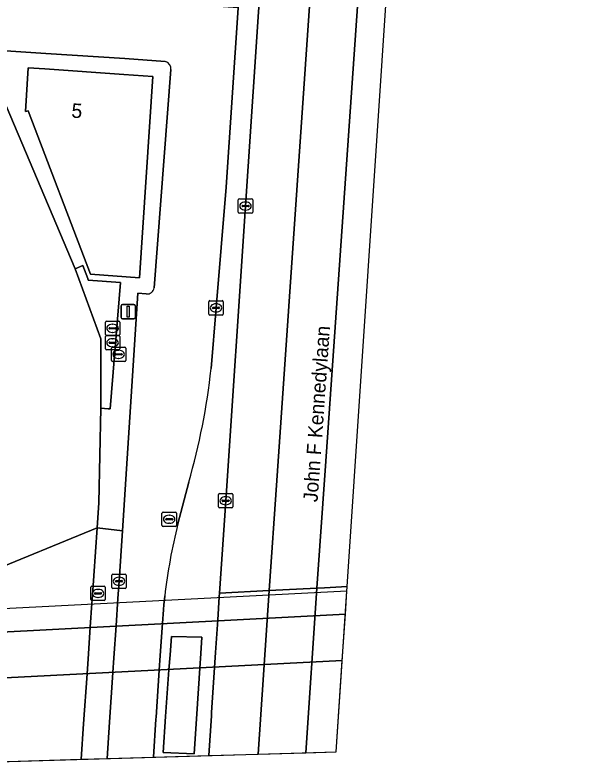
# Model space of a CAD drawing. Extents: x 161084 to 161928, y 385354 to 386522.
# Drawn here: x 161826.1 to 161866, y 385382.7 to 385434.6 of the extents above; entities that cross this region are included whole.
import ezdxf

# ---------------------------------------------------------------- set-up
doc = ezdxf.new("R2010")
doc.units = 0
for name, color, linetype in [('IMGEO_Berm_groen', 7, 'Continuous'), ('IMGEO_Berm_open', 7, 'Continuous'), ('IMGEO_Dek', 7, 'Continuous'), ('IMGEO_Fietspad_gesloten', 7, 'Continuous'), ('IMGEO_Kolk', 7, 'Continuous'), ('IMGEO_Lichtmast', 7, 'Continuous'), ('IMGEO_Openbare_ruimte_label', 7, 'Continuous'), ('IMGEO_Pand', 7, 'Continuous'), ('IMGEO_Pand_nummerreeks', 7, 'Continuous'), ('IMGEO_Pijler', 7, 'Continuous'), ('IMGEO_Rijbaan_lokaal_gesloten', 7, 'Continuous'), ('IMGEO_Rijbaan_lokaal_open', 7, 'Continuous'), ('IMGEO_Rijbaan_regionaal_gesloten', 7, 'Continuous'), ('IMGEO_Rioolput', 7, 'Continuous'), ('IMGEO_Terreindeel_open', 7, 'Continuous'), ('IMGEO_Voetpad_gesloten', 7, 'Continuous'), ('IMGEO_Voetpad_open', 7, 'Continuous')]:
    doc.layers.add(name, color=color, linetype=linetype)

msp = doc.modelspace()

# ---------------------------------------------------------------- linework, layer by layer
at = {"layer": 'IMGEO_Berm_groen'}
msp.add_lwpolyline([(161825.32, 385406.42), (161823.9, 385395.702), (161831.815, 385398.932), (161831.934, 385400.658), (161832.079, 385407.241), (161832.079, 385412.061), (161830.301, 385416.92), (161824.454, 385430.65), (161824.424, 385432.14), (161824.225, 385436.183), (161824.284, 385438.46), (161825.312, 385447.692), (161826.012, 385452.879), (161826.576, 385455.009), (161827.549, 385454.732), (161828.52, 385458.222), (161833.131, 385474.795), (161836.157, 385474.321), (161836.649, 385474.584), (161839.053, 385476.363)], dxfattribs=at)
at = {"layer": 'IMGEO_Berm_open'}
for points in [[(161839.562, 385383.109), (161839.747, 385385.876), (161839.761, 385386.097), (161839.971, 385389.239), (161840.039, 385390.264), (161840.191, 385392.532), (161840.297, 385394.134), (161840.315, 385394.398), (161840.742, 385400.813), (161842.12, 385421.284), (161843.55, 385442.735), (161844.924, 385463.175), (161845.309, 385468.395)], [(161843.117, 385463.877), (161843.398, 385461.787), (161842.893, 385454.265), (161841.605, 385435.058), (161840.769, 385422.585), (161840.069, 385414.21), (161839.728, 385410.002)], [(161838.182, 385402.099), (161837.422, 385399.201)], [(161836.513, 385394.202), (161836.485, 385393.943), (161836.45, 385393.596), (161836.418, 385393.248), (161836.354, 385392.313), (161836.201, 385390.073), (161836.131, 385389.042), (161835.908, 385385.774), (161835.899, 385385.636), (161835.718, 385382.998), (161839.562, 385383.109)]]:
    msp.add_lwpolyline(points, dxfattribs=at)
msp.add_lwpolyline([(161836.396, 385383.329), (161836.573, 385385.83), (161836.804, 385389.076), (161836.877, 385390.107), (161836.968, 385391.392), (161839.077, 385391.33), (161839.004, 385390.213), (161838.936, 385389.186), (161838.727, 385386.01), (161838.545, 385383.246)], close=True, dxfattribs=at)
for centre, radius, start, end in [((161792.28, 385415.181), 47.73, 344.0924, 353.7706), ((161874.83, 385389.817), 38.568, 165.9173, 173.471)]:
    msp.add_arc(centre, radius, start, end, dxfattribs=at)
at = {"layer": 'IMGEO_Dek'}
msp.add_lwpolyline([(161824.116, 385382.664), (161848.414, 385383.364), (161849.156, 385394.524), (161824.831, 385393.274), (161824.722, 385391.662), (161824.508, 385388.475)], close=True, dxfattribs=at)
at = {"layer": 'IMGEO_Fietspad_gesloten'}
msp.add_lwpolyline([(161848.836, 385389.717), (161849.05, 385392.931), (161824.722, 385391.662), (161824.508, 385388.475)], close=True, dxfattribs=at)
at = {"layer": 'IMGEO_Kolk'}
for p, q in [((161841.617, 385420.857), (161841.617, 385421.709)), ((161841.692, 385421.783), (161842.544, 385421.783)), ((161842.105, 385421.563), (161842.13, 385421.563)), ((161842.618, 385421.709), (161842.618, 385420.857)), ((161841.876, 385421.277), (161841.876, 385421.289)), ((161842.314, 385421.24), (161841.916, 385421.24)), ((161841.919, 385421.326), (161842.317, 385421.326)), ((161842.128, 385421.003), (161842.103, 385421.003)), ((161842.36, 385421.289), (161842.36, 385421.277)), ((161842.544, 385420.783), (161841.692, 385420.783)), ((161839.569, 385413.784), (161839.569, 385414.636)), ((161839.644, 385414.71), (161840.496, 385414.71)), ((161840.57, 385414.636), (161840.57, 385413.784)), ((161839.828, 385414.204), (161839.828, 385414.216)), ((161840.266, 385414.167), (161839.868, 385414.167)), ((161839.871, 385414.253), (161840.269, 385414.253)), ((161840.057, 385414.49), (161840.082, 385414.49)), ((161840.312, 385414.216), (161840.312, 385414.204)), ((161840.496, 385413.71), (161839.644, 385413.71)), ((161840.08, 385413.93), (161840.055, 385413.93)), ((161832.808, 385410.555), (161832.808, 385411.407)), ((161832.883, 385411.481), (161833.735, 385411.481)), ((161833.067, 385410.975), (161833.067, 385410.987)), ((161833.11, 385411.024), (161833.508, 385411.024)), ((161833.296, 385411.261), (161833.321, 385411.261)), ((161833.551, 385410.987), (161833.551, 385410.975)), ((161833.809, 385411.407), (161833.809, 385410.555)), ((161833.735, 385410.481), (161832.883, 385410.481)), ((161833.505, 385410.938), (161833.107, 385410.938)), ((161833.319, 385410.701), (161833.294, 385410.701)), ((161840.24, 385400.387), (161840.24, 385401.239)), ((161840.315, 385401.313), (161841.167, 385401.313)), ((161841.241, 385401.239), (161841.241, 385400.387)), ((161840.499, 385400.807), (161840.499, 385400.819)), ((161840.937, 385400.77), (161840.539, 385400.77)), ((161840.542, 385400.856), (161840.94, 385400.856)), ((161840.728, 385401.093), (161840.753, 385401.093)), ((161840.983, 385400.819), (161840.983, 385400.807)), ((161841.167, 385400.313), (161840.315, 385400.313)), ((161840.751, 385400.533), (161840.726, 385400.533)), ((161832.835, 385394.797), (161832.835, 385395.649)), ((161832.91, 385395.723), (161833.762, 385395.723)), ((161833.323, 385395.503), (161833.348, 385395.503)), ((161833.836, 385395.649), (161833.836, 385394.797)), ((161833.094, 385395.217), (161833.094, 385395.229)), ((161833.532, 385395.18), (161833.134, 385395.18)), ((161833.137, 385395.266), (161833.535, 385395.266)), ((161833.346, 385394.943), (161833.321, 385394.943)), ((161833.578, 385395.229), (161833.578, 385395.217)), ((161831.379, 385393.95), (161831.379, 385394.802)), ((161831.454, 385394.876), (161832.306, 385394.876)), ((161831.638, 385394.37), (161831.638, 385394.382)), ((161831.681, 385394.419), (161832.079, 385394.419)), ((161831.867, 385394.656), (161831.892, 385394.656)), ((161832.122, 385394.382), (161832.122, 385394.37)), ((161832.38, 385394.802), (161832.38, 385393.95)), ((161833.762, 385394.723), (161832.91, 385394.723)), ((161832.306, 385393.876), (161831.454, 385393.876)), ((161832.076, 385394.333), (161831.678, 385394.333)), ((161831.89, 385394.096), (161831.865, 385394.096))]:
    msp.add_line(p, q, dxfattribs=at)
for points in [[(161841.617, 385420.857), (161841.617, 385421.709)], [(161841.692, 385421.783), (161842.544, 385421.783)], [(161842.618, 385421.709), (161842.618, 385420.857)], [(161842.544, 385420.783), (161841.692, 385420.783)], [(161839.569, 385413.784), (161839.569, 385414.636)], [(161839.644, 385414.71), (161840.496, 385414.71)], [(161840.57, 385414.636), (161840.57, 385413.784)], [(161840.496, 385413.71), (161839.644, 385413.71)], [(161832.808, 385410.555), (161832.808, 385411.407)], [(161832.883, 385411.481), (161833.735, 385411.481)], [(161833.809, 385411.407), (161833.809, 385410.555)], [(161833.735, 385410.481), (161832.883, 385410.481)], [(161840.24, 385400.387), (161840.24, 385401.239)], [(161840.315, 385401.313), (161841.167, 385401.313)], [(161841.241, 385401.239), (161841.241, 385400.387)], [(161841.167, 385400.313), (161840.315, 385400.313)], [(161832.835, 385394.797), (161832.835, 385395.649)], [(161832.91, 385395.723), (161833.762, 385395.723)], [(161833.836, 385395.649), (161833.836, 385394.797)], [(161831.379, 385393.95), (161831.379, 385394.802)], [(161831.454, 385394.876), (161832.306, 385394.876)], [(161832.38, 385394.802), (161832.38, 385393.95)], [(161833.762, 385394.723), (161832.91, 385394.723)], [(161832.306, 385393.876), (161831.454, 385393.876)]]:
    msp.add_lwpolyline(points, dxfattribs=at)
for centre, radius, start, end in [((161841.694, 385421.707), 0.0765, 91.552, 178.448), ((161841.694, 385421.707), 0.0765, 91.552, 178.448), ((161842.542, 385421.707), 0.0765, 1.552, 88.448), ((161842.542, 385421.707), 0.0765, 1.552, 88.448), ((161841.694, 385420.859), 0.0765, 181.552, 268.448), ((161841.694, 385420.859), 0.0765, 181.552, 268.448), ((161841.916, 385421.286), 0.0403, 85.8775, 175.7526), ((161841.913, 385421.276), 0.0366, 178.938, 274.7102), ((161842.317, 385421.283), 0.043, 264.8664, 352.4533), ((161842.321, 385421.288), 0.0386, 1.7309, 96.639), ((161842.542, 385420.859), 0.0765, 271.552, 358.448), ((161842.542, 385420.859), 0.0765, 271.552, 358.448), ((161839.646, 385414.634), 0.0765, 91.552, 178.448), ((161839.646, 385414.634), 0.0765, 91.552, 178.448), ((161840.494, 385414.634), 0.0765, 1.552, 88.448), ((161840.494, 385414.634), 0.0765, 1.552, 88.448), ((161839.868, 385414.213), 0.0403, 85.8775, 175.7526), ((161839.865, 385414.203), 0.0366, 178.938, 274.7102), ((161840.269, 385414.21), 0.043, 264.8664, 352.4533), ((161840.273, 385414.215), 0.0386, 1.7309, 96.639), ((161839.646, 385413.786), 0.0765, 181.552, 268.448), ((161839.646, 385413.786), 0.0765, 181.552, 268.448), ((161840.494, 385413.786), 0.0765, 271.552, 358.448), ((161840.494, 385413.786), 0.0765, 271.552, 358.448), ((161832.885, 385411.405), 0.0765, 91.552, 178.448), ((161832.885, 385411.405), 0.0765, 91.552, 178.448), ((161833.107, 385410.984), 0.0403, 85.8775, 175.7526), ((161833.512, 385410.986), 0.0386, 1.7309, 96.639), ((161833.733, 385411.405), 0.0765, 1.552, 88.448), ((161833.733, 385411.405), 0.0765, 1.552, 88.448), ((161832.885, 385410.557), 0.0765, 181.552, 268.448), ((161832.885, 385410.557), 0.0765, 181.552, 268.448), ((161833.104, 385410.974), 0.0366, 178.938, 274.7102), ((161833.508, 385410.981), 0.043, 264.8664, 352.4533), ((161833.733, 385410.557), 0.0765, 271.552, 358.448), ((161833.733, 385410.557), 0.0765, 271.552, 358.448), ((161840.317, 385401.237), 0.0765, 91.552, 178.448), ((161840.317, 385401.237), 0.0765, 91.552, 178.448), ((161841.165, 385401.237), 0.0765, 1.552, 88.448), ((161841.165, 385401.237), 0.0765, 1.552, 88.448), ((161840.539, 385400.816), 0.0403, 85.8775, 175.7526), ((161840.536, 385400.806), 0.0366, 178.938, 274.7102), ((161840.94, 385400.813), 0.043, 264.8664, 352.4533), ((161840.944, 385400.818), 0.0386, 1.7309, 96.639), ((161840.317, 385400.389), 0.0765, 181.552, 268.448), ((161840.317, 385400.389), 0.0765, 181.552, 268.448), ((161841.165, 385400.389), 0.0765, 271.552, 358.448), ((161841.165, 385400.389), 0.0765, 271.552, 358.448), ((161832.912, 385395.647), 0.0765, 91.552, 178.448), ((161832.912, 385395.647), 0.0765, 91.552, 178.448), ((161833.76, 385395.647), 0.0765, 1.552, 88.448), ((161833.76, 385395.647), 0.0765, 1.552, 88.448), ((161833.134, 385395.226), 0.0403, 85.8775, 175.7526), ((161833.131, 385395.216), 0.0366, 178.938, 274.7102), ((161833.535, 385395.223), 0.043, 264.8664, 352.4533), ((161833.539, 385395.228), 0.0386, 1.7309, 96.639), ((161831.456, 385394.8), 0.0765, 91.552, 178.448), ((161831.456, 385394.8), 0.0765, 91.552, 178.448), ((161831.678, 385394.379), 0.0403, 85.8775, 175.7526), ((161832.083, 385394.381), 0.0386, 1.7309, 96.639), ((161832.304, 385394.8), 0.0765, 1.552, 88.448), ((161832.304, 385394.8), 0.0765, 1.552, 88.448), ((161832.912, 385394.799), 0.0765, 181.552, 268.448), ((161832.912, 385394.799), 0.0765, 181.552, 268.448), ((161833.76, 385394.799), 0.0765, 271.552, 358.448), ((161833.76, 385394.799), 0.0765, 271.552, 358.448), ((161831.456, 385393.952), 0.0765, 181.552, 268.448), ((161831.456, 385393.952), 0.0765, 181.552, 268.448), ((161831.675, 385394.369), 0.0366, 178.938, 274.7102), ((161832.079, 385394.376), 0.043, 264.8664, 352.4533), ((161832.304, 385393.952), 0.0765, 271.552, 358.448), ((161832.304, 385393.952), 0.0765, 271.552, 358.448)]:
    msp.add_arc(centre, radius, start, end, dxfattribs=at)
for centre, major_axis, ratio, start_param, end_param in [((161842.104, 385421.283), (-0.387, 0.002), 0.722429, 4.712389, 7.853982), ((161842.129, 385421.283), (-0.39, 0.002), 0.717154, 1.570796, 4.712389), ((161840.056, 385414.21), (-0.387, 0.002), 0.722429, 4.712389, 7.853982), ((161840.081, 385414.21), (-0.39, 0.002), 0.717154, 1.570796, 4.712389), ((161833.295, 385410.981), (-0.387, 0.002), 0.722429, 4.712389, 7.853982), ((161833.32, 385410.981), (-0.39, 0.002), 0.717154, 1.570796, 4.712389), ((161840.727, 385400.813), (-0.387, 0.002), 0.722429, 4.712389, 7.853982), ((161840.752, 385400.813), (-0.39, 0.002), 0.717154, 1.570796, 4.712389), ((161833.322, 385395.223), (-0.387, 0.002), 0.722429, 4.712389, 7.853982), ((161833.347, 385395.223), (-0.39, 0.002), 0.717154, 1.570796, 4.712389), ((161831.866, 385394.376), (-0.387, 0.002), 0.722429, 4.712389, 7.853982), ((161831.891, 385394.376), (-0.39, 0.002), 0.717154, 1.570796, 4.712389)]:
    msp.add_ellipse(centre, major_axis=major_axis, ratio=ratio, start_param=start_param, end_param=end_param, dxfattribs=at)
at = {"layer": 'IMGEO_Lichtmast'}
for p, q in [((161833.481, 385413.55), (161833.481, 385414.35)), ((161833.481, 385414.35), (161833.481, 385413.55)), ((161833.581, 385414.45), (161834.371, 385414.45)), ((161834.371, 385414.45), (161833.581, 385414.45)), ((161834.471, 385414.35), (161834.471, 385413.55)), ((161834.471, 385413.55), (161834.471, 385414.35)), ((161834.371, 385413.45), (161833.581, 385413.45)), ((161833.581, 385413.45), (161834.371, 385413.45))]:
    msp.add_line(p, q, dxfattribs=at)
msp.add_lwpolyline([(161833.901, 385414.325), (161834.051, 385414.325), (161834.051, 385413.575), (161833.901, 385413.575), (161833.901, 385414.325)], dxfattribs=at)
for centre, start, end in [((161833.581, 385414.35), 90, 180), ((161833.581, 385414.35), 90, 180), ((161834.371, 385414.35), 0, 90), ((161834.371, 385414.35), 360, 90), ((161833.581, 385413.55), 180, 270), ((161833.581, 385413.55), 180, 270), ((161834.371, 385413.55), 270, 0), ((161834.371, 385413.55), 270, 0)]:
    msp.add_arc(centre, 0.1, start, end, dxfattribs=at)
at = {"layer": 'IMGEO_Pand'}
msp.add_lwpolyline([(161828.192, 385430.811), (161827.017, 385430.893), (161826.832, 385427.839), (161827.018, 385427.903), (161831.363, 385416.554), (161834.761, 385416.296), (161835.693, 385430.288), (161833.672, 385430.429)], close=True, dxfattribs=at)
at = {"layer": 'IMGEO_Pijler'}
msp.add_lwpolyline([(161838.936, 385389.186), (161839.004, 385390.213), (161839.077, 385391.33), (161836.968, 385391.392), (161836.877, 385390.107), (161836.804, 385389.076), (161836.573, 385385.83), (161836.396, 385383.329), (161838.545, 385383.246), (161838.727, 385386.01)], close=True, dxfattribs=at)
at = {"layer": 'IMGEO_Rijbaan_lokaal_gesloten'}
msp.add_lwpolyline([(161824.116, 385382.664), (161848.414, 385383.364), (161848.836, 385389.717), (161824.508, 385388.475)], close=True, dxfattribs=at)
at = {"layer": 'IMGEO_Rijbaan_lokaal_open'}
for points in [[(161839.728, 385410.002), (161840.069, 385414.21), (161840.769, 385422.585), (161841.605, 385435.058), (161833.972, 385435.565), (161828.511, 385435.928), (161824.225, 385436.183), (161824.424, 385432.14), (161828.258, 385431.877), (161833.735, 385431.519), (161836.547, 385431.325)], [(161836.933, 385430.763), (161835.786, 385415.597)], [(161835.223, 385415.179), (161834.635, 385415.241), (161834.264, 385409.491), (161833.579, 385398.725), (161833.338, 385395.224), (161833.258, 385394.034), (161833.13, 385392.129), (161832.981, 385389.913), (161832.911, 385388.876), (161832.679, 385385.435), (161832.509, 385382.906), (161835.718, 385382.998)], [(161837.422, 385399.201), (161838.182, 385402.099)], [(161835.718, 385382.998), (161835.899, 385385.636), (161835.908, 385385.774), (161836.131, 385389.042), (161836.201, 385390.073), (161836.354, 385392.313), (161836.418, 385393.248), (161836.45, 385393.596), (161836.485, 385393.943), (161836.513, 385394.202)]]:
    msp.add_lwpolyline(points, dxfattribs=at)
for centre, radius, start, end in [((161836.439, 385430.838), 0.499, 351.412, 77.5531), ((161835.283, 385415.687), 0.511, 263.31, 349.8741), ((161792.28, 385415.181), 47.73, 344.0924, 353.7706), ((161874.83, 385389.817), 38.568, 165.9173, 173.471)]:
    msp.add_arc(centre, radius, start, end, dxfattribs=at)
at = {"layer": 'IMGEO_Rijbaan_regionaal_gesloten'}
for points in [[(161856.595, 385582.716), (161860.496, 385647.553), (161857.561, 385647.676), (161852.852, 385580.501), (161851.17, 385555.782), (161847.762, 385499.902), (161846.425, 385479.865), (161845.309, 385468.395), (161844.924, 385463.175), (161843.55, 385442.735), (161842.12, 385421.284), (161840.742, 385400.813), (161840.315, 385394.398), (161843.769, 385394.576), (161844.294, 385402.219), (161851.574, 385508.138)], [(161864.225, 385647.376), (161860.496, 385647.553), (161856.595, 385582.716), (161851.574, 385508.138), (161844.294, 385402.219), (161843.769, 385394.576), (161847.08, 385394.747), (161847.695, 385403.564), (161852.193, 385468.095), (161854.711, 385505.621)], [(161849.178, 385394.855), (161861.764, 385584.094), (161865.968, 385647.294), (161864.225, 385647.376), (161854.711, 385505.621), (161852.193, 385468.095), (161847.695, 385403.564), (161847.08, 385394.747), (161847.608, 385394.774)], [(161839.562, 385383.109), (161843.005, 385383.208), (161843.769, 385394.576), (161840.315, 385394.398), (161840.297, 385394.134), (161840.191, 385392.532), (161840.039, 385390.264), (161839.971, 385389.239), (161839.761, 385386.097), (161839.747, 385385.876)], [(161843.005, 385383.208), (161846.294, 385383.303), (161847.08, 385394.747), (161843.769, 385394.576)]]:
    msp.add_lwpolyline(points, close=True, dxfattribs=at)
msp.add_lwpolyline([(161846.294, 385383.303), (161848.414, 385383.364), (161849.178, 385394.855), (161847.608, 385394.774), (161847.08, 385394.747), (161846.294, 385383.303)], dxfattribs=at)
at = {"layer": 'IMGEO_Rioolput'}
for p, q in [((161832.387, 385412.364), (161832.387, 385413.216)), ((161832.462, 385413.29), (161833.314, 385413.29)), ((161832.875, 385413.07), (161832.9, 385413.07)), ((161833.388, 385413.216), (161833.388, 385412.364)), ((161832.646, 385412.784), (161832.646, 385412.796)), ((161833.084, 385412.747), (161832.686, 385412.747)), ((161832.689, 385412.833), (161833.087, 385412.833)), ((161833.13, 385412.796), (161833.13, 385412.784)), ((161832.386, 385411.363), (161832.386, 385412.215)), ((161832.461, 385412.289), (161833.313, 385412.289)), ((161833.314, 385412.29), (161832.462, 385412.29)), ((161832.898, 385412.51), (161832.873, 385412.51)), ((161832.874, 385412.069), (161832.899, 385412.069)), ((161833.387, 385412.215), (161833.387, 385411.363)), ((161832.645, 385411.783), (161832.645, 385411.795)), ((161833.083, 385411.746), (161832.685, 385411.746)), ((161832.688, 385411.832), (161833.086, 385411.832)), ((161832.897, 385411.509), (161832.872, 385411.509)), ((161833.129, 385411.795), (161833.129, 385411.783)), ((161833.313, 385411.289), (161832.461, 385411.289)), ((161836.319, 385399.1), (161836.319, 385399.952)), ((161836.394, 385400.026), (161837.246, 385400.026)), ((161836.621, 385399.569), (161837.019, 385399.569)), ((161836.807, 385399.806), (161836.832, 385399.806)), ((161837.32, 385399.952), (161837.32, 385399.1)), ((161836.578, 385399.52), (161836.578, 385399.532)), ((161837.016, 385399.483), (161836.618, 385399.483)), ((161836.83, 385399.246), (161836.805, 385399.246)), ((161837.062, 385399.532), (161837.062, 385399.52)), ((161837.246, 385399.026), (161836.394, 385399.026))]:
    msp.add_line(p, q, dxfattribs=at)
for points in [[(161832.387, 385412.364), (161832.387, 385413.216)], [(161832.462, 385413.29), (161833.314, 385413.29)], [(161833.388, 385413.216), (161833.388, 385412.364)], [(161832.386, 385411.363), (161832.386, 385412.215)], [(161832.461, 385412.289), (161833.313, 385412.289)], [(161833.314, 385412.29), (161832.462, 385412.29)], [(161833.387, 385412.215), (161833.387, 385411.363)], [(161833.313, 385411.289), (161832.461, 385411.289)], [(161836.319, 385399.1), (161836.319, 385399.952)], [(161836.394, 385400.026), (161837.246, 385400.026)], [(161837.32, 385399.952), (161837.32, 385399.1)], [(161837.246, 385399.026), (161836.394, 385399.026)]]:
    msp.add_lwpolyline(points, dxfattribs=at)
for centre, radius, start, end in [((161832.464, 385413.214), 0.0765, 91.552, 178.448), ((161832.464, 385413.214), 0.0765, 91.552, 178.448), ((161833.312, 385413.214), 0.0765, 1.552, 88.448), ((161833.312, 385413.214), 0.0765, 1.552, 88.448), ((161832.686, 385412.793), 0.0403, 85.8775, 175.7526), ((161832.683, 385412.783), 0.0366, 178.938, 274.7102), ((161833.087, 385412.79), 0.043, 264.8664, 352.4533), ((161833.091, 385412.795), 0.0386, 1.7309, 96.639), ((161832.463, 385412.213), 0.0765, 91.552, 178.448), ((161832.463, 385412.213), 0.0765, 91.552, 178.448), ((161832.464, 385412.366), 0.0765, 181.552, 268.448), ((161832.464, 385412.366), 0.0765, 181.552, 268.448), ((161833.311, 385412.213), 0.0765, 1.552, 88.448), ((161833.311, 385412.213), 0.0765, 1.552, 88.448), ((161833.312, 385412.366), 0.0765, 271.552, 358.448), ((161833.312, 385412.366), 0.0765, 271.552, 358.448), ((161832.685, 385411.792), 0.0403, 85.8775, 175.7526), ((161832.682, 385411.782), 0.0366, 178.938, 274.7102), ((161833.086, 385411.789), 0.043, 264.8664, 352.4533), ((161833.09, 385411.794), 0.0386, 1.7309, 96.639), ((161832.463, 385411.365), 0.0765, 181.552, 268.448), ((161832.463, 385411.365), 0.0765, 181.552, 268.448), ((161833.311, 385411.365), 0.0765, 271.552, 358.448), ((161833.311, 385411.365), 0.0765, 271.552, 358.448), ((161836.396, 385399.95), 0.0765, 91.552, 178.448), ((161836.396, 385399.95), 0.0765, 91.552, 178.448), ((161836.618, 385399.529), 0.0403, 85.8775, 175.7526), ((161837.023, 385399.531), 0.0386, 1.7309, 96.639), ((161837.244, 385399.95), 0.0765, 1.552, 88.448), ((161837.244, 385399.95), 0.0765, 1.552, 88.448), ((161836.396, 385399.102), 0.0765, 181.552, 268.448), ((161836.396, 385399.102), 0.0765, 181.552, 268.448), ((161836.615, 385399.519), 0.0366, 178.938, 274.7102), ((161837.019, 385399.526), 0.043, 264.8664, 352.4533), ((161837.244, 385399.102), 0.0765, 271.552, 358.448), ((161837.244, 385399.102), 0.0765, 271.552, 358.448)]:
    msp.add_arc(centre, radius, start, end, dxfattribs=at)
for centre, major_axis, ratio, start_param, end_param in [((161832.874, 385412.79), (-0.387, 0.002), 0.722429, 4.712389, 7.853982), ((161832.899, 385412.79), (-0.39, 0.002), 0.717154, 1.570796, 4.712389), ((161832.873, 385411.789), (-0.387, 0.002), 0.722429, 4.712389, 7.853982), ((161832.898, 385411.789), (-0.39, 0.002), 0.717154, 1.570796, 4.712389), ((161836.806, 385399.526), (-0.387, 0.002), 0.722429, 4.712389, 7.853982), ((161836.831, 385399.526), (-0.39, 0.002), 0.717154, 1.570796, 4.712389)]:
    msp.add_ellipse(centre, major_axis=major_axis, ratio=ratio, start_param=start_param, end_param=end_param, dxfattribs=at)
at = {"layer": 'IMGEO_Terreindeel_open'}
msp.add_lwpolyline([(161824.116, 385382.664), (161830.706, 385382.854), (161830.876, 385385.322), (161831.114, 385388.784), (161831.186, 385389.824), (161831.338, 385392.027), (161831.453, 385393.69), (161831.47, 385393.941), (161831.815, 385398.932), (161823.9, 385395.702), (161823.959, 385393.553), (161823.265, 385393.517), (161823.213, 385393.277), (161823.21, 385393.242), (161823.323, 385393.2), (161824.239, 385393.244), (161824.27, 385393.246), (161824.545, 385393.26), (161824.831, 385393.274), (161824.722, 385391.662), (161824.705, 385391.408), (161824.576, 385389.495), (161824.508, 385388.475)], close=True, dxfattribs=at)
at = {"layer": 'IMGEO_Voetpad_gesloten'}
msp.add_lwpolyline([(161849.05, 385392.931), (161849.156, 385394.524), (161824.831, 385393.274), (161824.722, 385391.662)], close=True, dxfattribs=at)
at = {"layer": 'IMGEO_Voetpad_open'}
for points in [[(161836.547, 385431.325), (161833.735, 385431.519), (161828.258, 385431.877), (161824.424, 385432.14), (161824.454, 385430.65), (161830.301, 385416.92), (161830.824, 385417.156), (161831.159, 385416.247), (161831.199, 385416.131), (161833.438, 385415.97), (161832.726, 385407.187), (161832.573, 385407.2), (161832.079, 385407.241), (161831.934, 385400.658), (161831.815, 385398.932), (161833.579, 385398.725), (161834.264, 385409.491)], [(161835.786, 385415.597), (161836.933, 385430.763)], [(161834.264, 385409.491), (161834.635, 385415.241), (161835.223, 385415.179)]]:
    msp.add_lwpolyline(points, dxfattribs=at)
for points in [[(161826.832, 385427.839), (161827.017, 385430.893), (161828.192, 385430.811), (161833.672, 385430.429), (161835.693, 385430.288), (161834.761, 385416.296), (161831.363, 385416.554), (161827.018, 385427.903)], [(161832.079, 385407.241), (161832.573, 385407.2), (161832.726, 385407.187), (161833.438, 385415.97), (161831.199, 385416.131), (161831.159, 385416.247), (161830.824, 385417.156), (161830.301, 385416.92), (161832.079, 385412.061)], [(161832.509, 385382.906), (161832.679, 385385.435), (161832.911, 385388.876), (161832.981, 385389.913), (161833.13, 385392.129), (161833.258, 385394.034), (161833.338, 385395.224), (161833.579, 385398.725), (161831.815, 385398.932), (161831.47, 385393.941), (161831.453, 385393.69), (161831.338, 385392.027), (161831.186, 385389.824), (161831.114, 385388.784), (161830.876, 385385.322), (161830.706, 385382.854)]]:
    msp.add_lwpolyline(points, close=True, dxfattribs=at)
for centre, radius, start, end in [((161836.439, 385430.838), 0.499, 351.412, 77.5531), ((161835.283, 385415.687), 0.511, 263.31, 349.8741)]:
    msp.add_arc(centre, radius, start, end, dxfattribs=at)

# ---------------------------------------------------------------- texts
at = {"layer": 'IMGEO_Openbare_ruimte_label'}
msp.add_text('John F Kennedylaan', height=1, rotation=85.9266, dxfattribs=at).set_placement((161847.115, 385400.694))
at = {"layer": 'IMGEO_Pand_nummerreeks'}
msp.add_text('5', height=1, rotation=356.0611, dxfattribs=at).set_placement((161830.008, 385427.428))

doc.saveas('drawing.dxf')
